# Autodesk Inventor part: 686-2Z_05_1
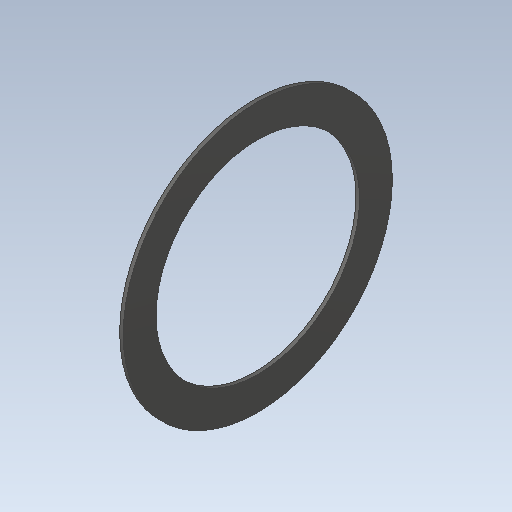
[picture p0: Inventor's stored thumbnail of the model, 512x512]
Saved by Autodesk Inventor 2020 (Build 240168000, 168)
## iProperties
Created: 2017-11
Part Number: 686-2Z_05_1
Material: Ogólny
Document SubType Name: Modeling
Designer: Tomasz
Density: 1 g/cm^3
Appearance: Domyślna
Sending System: SolidWorks 2017
Last Author: Tomasz
Last Saved: 2017-11-19
Source: 686-2Z_05_1
Author: Tomasz
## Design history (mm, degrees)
feature "Imported1"
node "Bryła1"
